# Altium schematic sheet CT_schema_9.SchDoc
size 386 x 278 mm
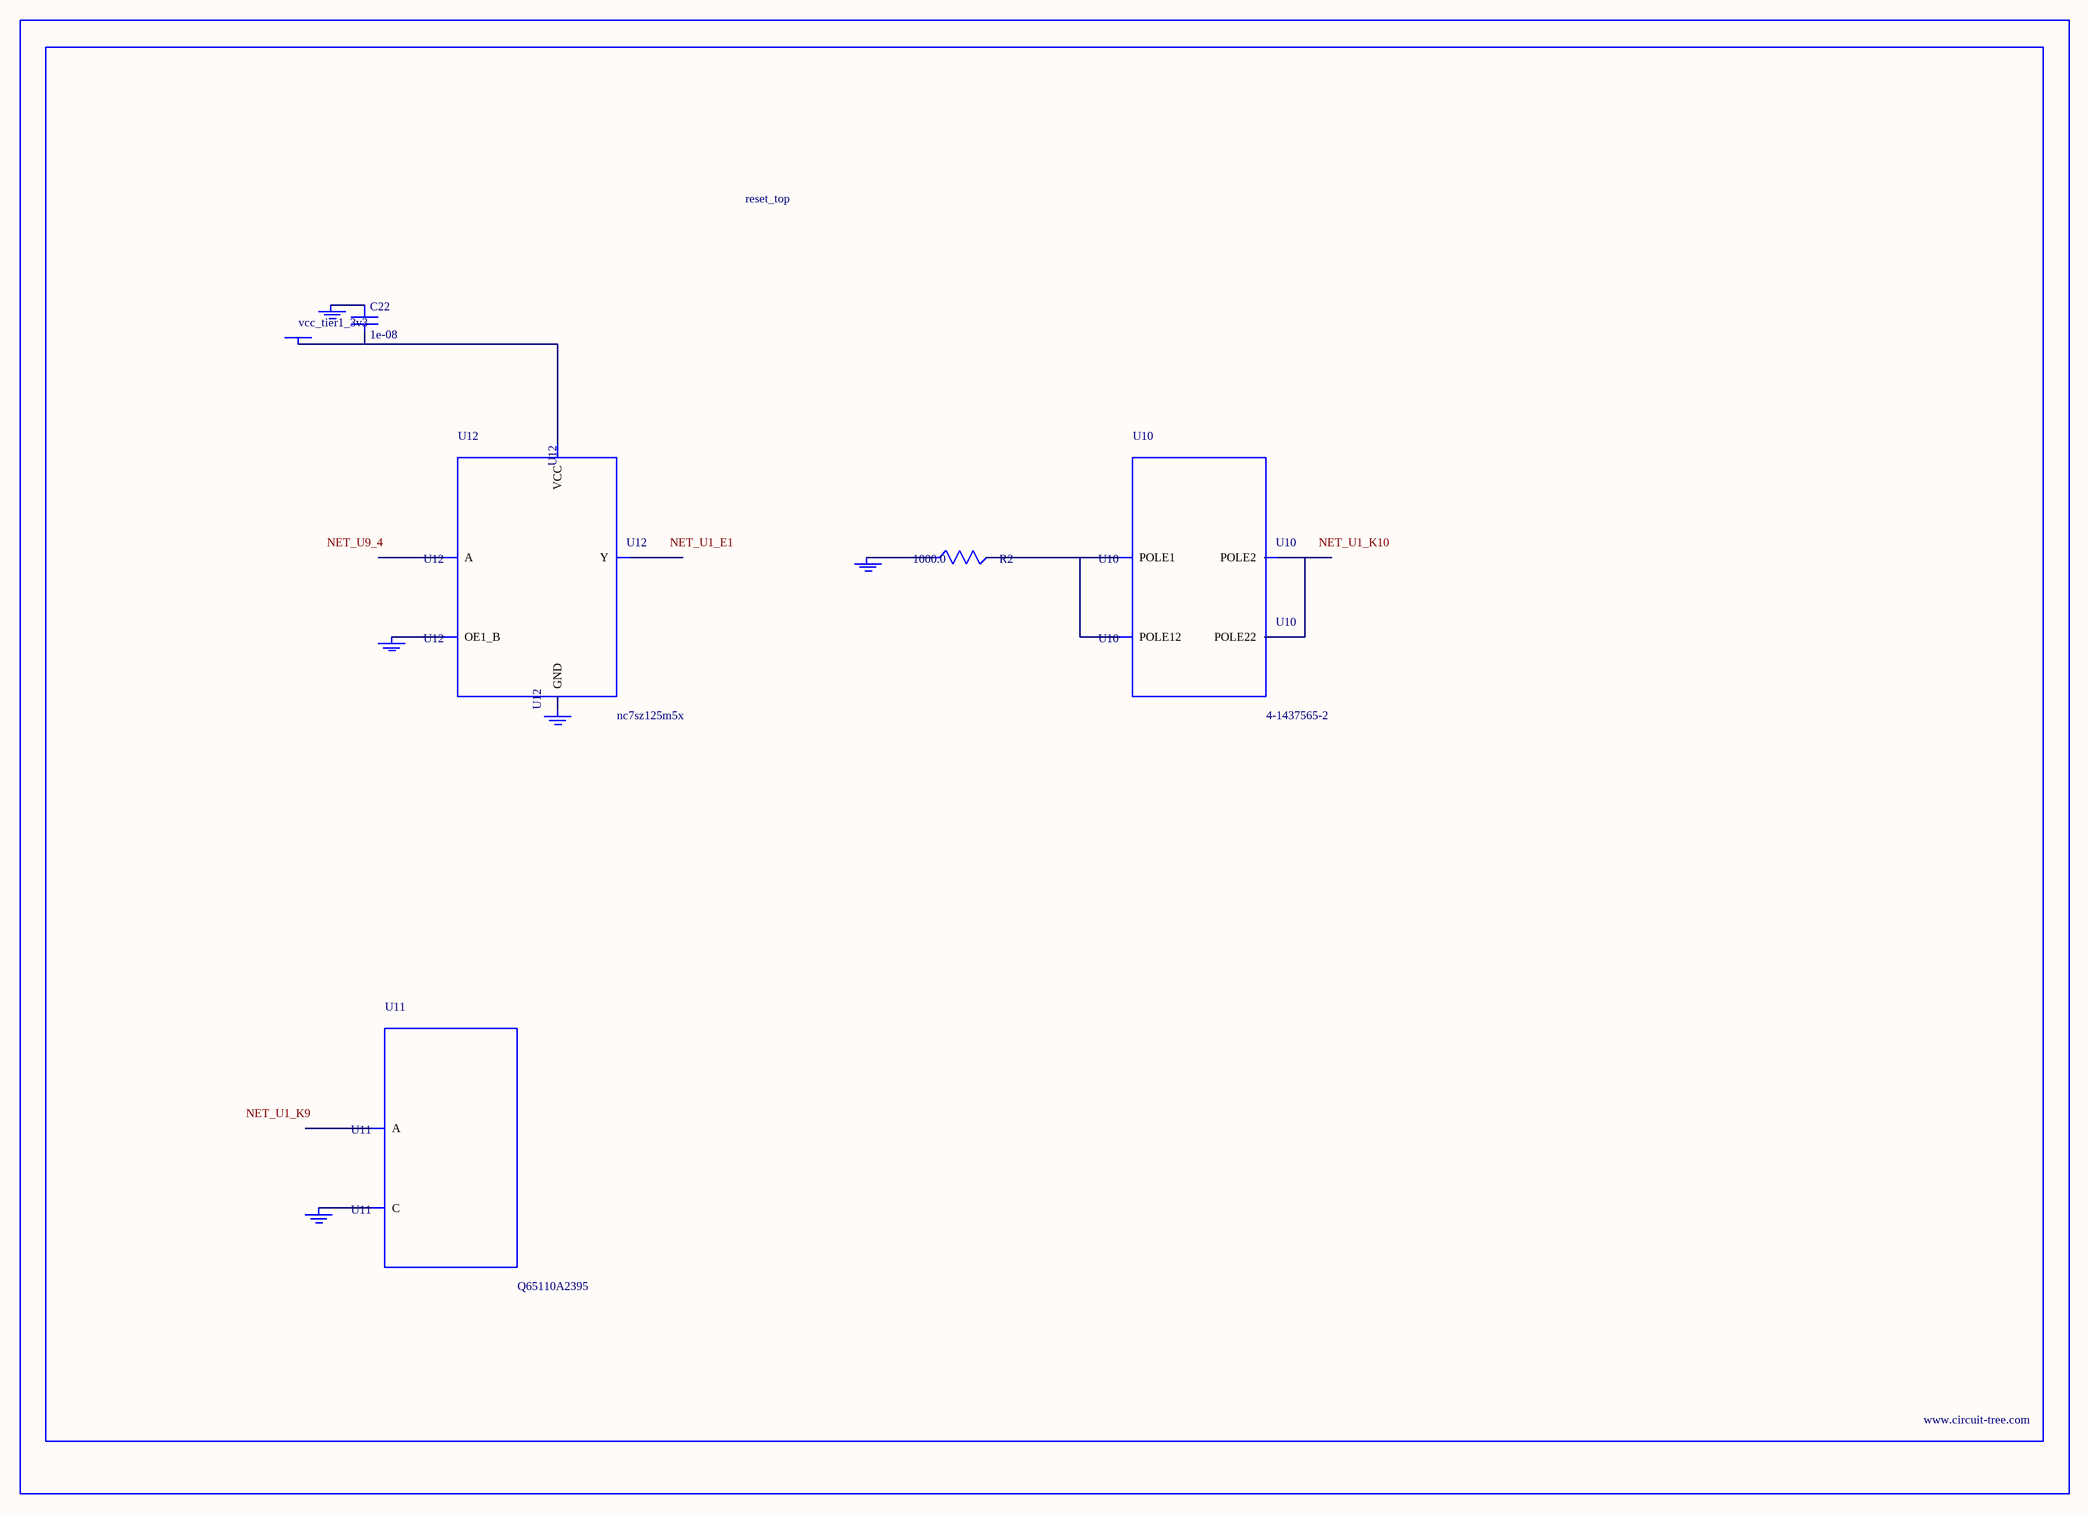
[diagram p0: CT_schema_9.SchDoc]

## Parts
BORDER8  (no value)
C22  1e-08  [C0402]
GND_INSTANCE_8_0  (no value)
GND_INSTANCE_8_1  (no value)
GND_INSTANCE_8_2  (no value)
GND_INSTANCE_8_3  (no value)
GND_INSTANCE_8_4  (no value)
POWER_INSTANCE_8_0  vcc_tier1_3v3
R2  1000.0  [R0603]
U10  4-1437565-2  [SW_4-1437565-2]
U11  Q65110A2395  [LGM67K-G1J2-24-Z]
U12  nc7sz125m5x  [NC7SZ125M5X]

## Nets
NetC22_1: C22.1 GND_INSTANCE_8_2.0(GND)
NetC22_2: C22.2 POWER_INSTANCE_8_0.0(PWR) U12.5(VCC)
NetGND_INSTANCE_8_0_0: GND_INSTANCE_8_0.0(GND) R2.1
NetGND_INSTANCE_8_1_0: GND_INSTANCE_8_1.0(GND) U11.C
NetGND_INSTANCE_8_3_0: GND_INSTANCE_8_3.0(GND) U12.1(OE1_B)
NetGND_INSTANCE_8_4_0: GND_INSTANCE_8_4.0(GND) U12.3(GND)
NetR2_2: R2.2 U10.1(POLE1) U10.2(POLE12)
NetU10_3: U10.3(POLE2) U10.4(POLE22)

Not connected (* = marked no-connect by the designer): U11 A; U12 2(A) 4(Y)

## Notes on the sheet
- Labels drawn without touching a wire or pin: NET_U1_E1, NET_U1_K9, NET_U1_K10, NET_U9_4

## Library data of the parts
BORDER8 = BORDER_PAGE8
C22 = C0402C103K3RAC
GND_INSTANCE_8_0-GND_INSTANCE_8_4 = GND
POWER_INSTANCE_8_0 = PWR
R2 = RC0603JR-071KL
